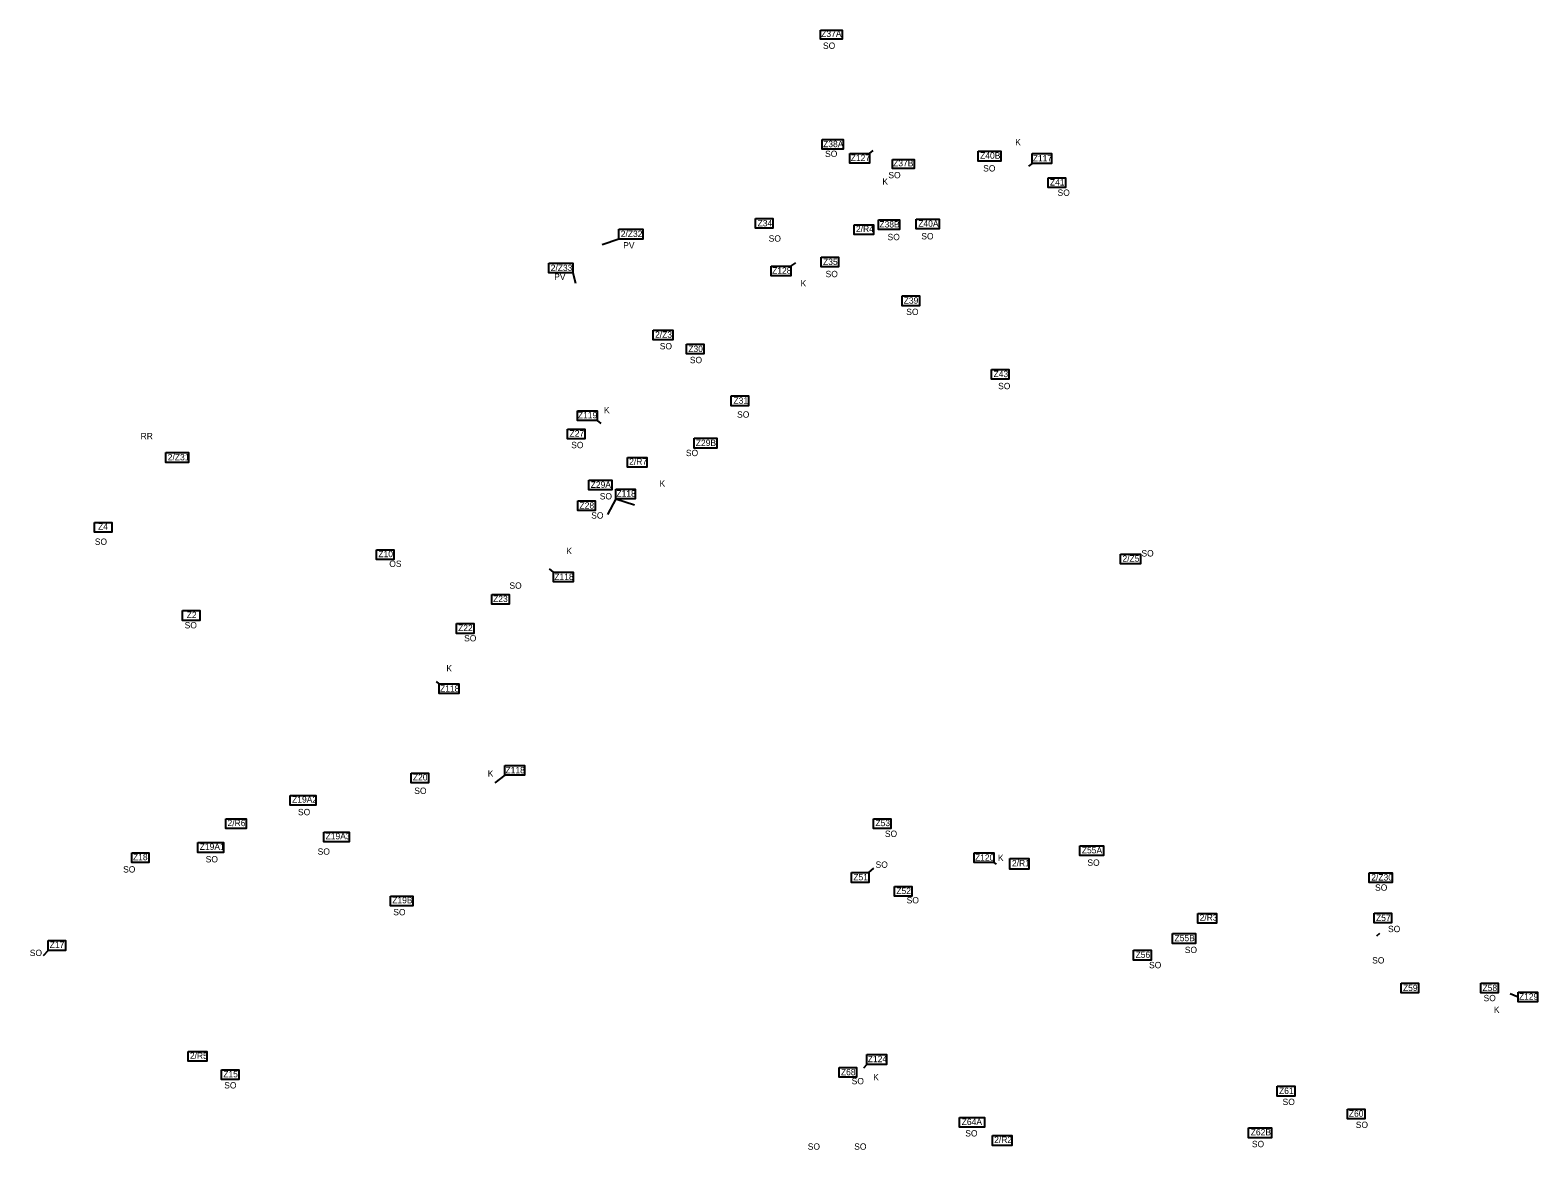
# Model space of a CAD drawing. Extents: x -443485 to -436070, y -1146628 to -1129894.
# Drawn here: x -443043 to -440666, y -1131659 to -1129894 of the extents above; entities that cross this region are included whole.
import ezdxf

# ---------------------------------------------------------------- set-up
doc = ezdxf.new("R2010")
doc.units = 0
for name, color, linetype in [('Vrstva 3', 7, 'Continuous'), ('Vrstva 4', 7, 'Continuous'), ('Vrstva 8', 7, 'Continuous')]:
    doc.layers.add(name, color=color, linetype=linetype)

msp = doc.modelspace()

# ---------------------------------------------------------------- linework, layer by layer
at = {"layer": 'Vrstva 3'}
for p, q in [((-442115.2, -1130223.5), (-442141.4, -1130232.8)), ((-442187.7, -1130277), (-442183.3, -1130293.2)), ((-441721, -1131222.3), (-441712.8, -1131215.4)), ((-443014.7, -1131344.8), (-443022.4, -1131353.5))]:
    msp.add_line(p, q, dxfattribs=at)
for points in [[(-441797.2, -1129894.2), (-441763, -1129894.2), (-441763, -1129908.3), (-441797.2, -1129908.3)], [(-441794.3, -1130066.6), (-441761.2, -1130066.6), (-441761.2, -1130082), (-441794.3, -1130082)], [(-441548.8, -1130085.1), (-441512.7, -1130085.1), (-441512.7, -1130100.5), (-441548.8, -1130100.5)], [(-441683.8, -1130098.2), (-441649.6, -1130098.2), (-441649.6, -1130112.3), (-441683.8, -1130112.3)], [(-441438.1, -1130126.8), (-441410.7, -1130126.8), (-441410.7, -1130142.2), (-441438.1, -1130142.2)], [(-441899.4, -1130191.2), (-441872.1, -1130191.2), (-441872.1, -1130206.6), (-441899.4, -1130206.6)], [(-441744, -1130200.9), (-441713.8, -1130200.9), (-441713.8, -1130216.3), (-441744, -1130216.3)], [(-441705.6, -1130193.1), (-441672.5, -1130193.1), (-441672.5, -1130208.5), (-441705.6, -1130208.5)], [(-441646.3, -1130192.2), (-441610.2, -1130192.2), (-441610.2, -1130207.6), (-441646.3, -1130207.6)], [(-442115.2, -1130208.1), (-442077.3, -1130208.1), (-442077.3, -1130223.5), (-442115.2, -1130223.5)], [(-441796.3, -1130252.1), (-441768.9, -1130252.1), (-441768.9, -1130267.5), (-441796.3, -1130267.5)], [(-442225.5, -1130261.6), (-442187.7, -1130261.6), (-442187.7, -1130277), (-442225.5, -1130277)], [(-441668.4, -1130313.2), (-441641, -1130313.2), (-441641, -1130328.6), (-441668.4, -1130328.6)], [(-442061.1, -1130366.9), (-442029.9, -1130366.9), (-442029.9, -1130382.3), (-442061.1, -1130382.3)], [(-442008.5, -1130389.3), (-441981.2, -1130389.3), (-441981.2, -1130404.7), (-442008.5, -1130404.7)], [(-441527.5, -1130428.9), (-441500.2, -1130428.9), (-441500.2, -1130444.3), (-441527.5, -1130444.3)], [(-441937.8, -1130470.9), (-441910.5, -1130470.9), (-441910.5, -1130486.3), (-441937.8, -1130486.3)], [(-442196.2, -1130523), (-442168.8, -1130523), (-442168.8, -1130538.4), (-442196.2, -1130538.4)], [(-441996.3, -1130537.6), (-441960.5, -1130537.6), (-441960.5, -1130553), (-441996.3, -1130553)], [(-442829.3, -1130560.1), (-442793.4, -1130560.1), (-442793.4, -1130575.5), (-442829.3, -1130575.5)], [(-442101.5, -1130567.8), (-442071, -1130567.8), (-442071, -1130583.2), (-442101.5, -1130583.2)], [(-442162.1, -1130603.5), (-442126, -1130603.5), (-442126, -1130618.9), (-442162.1, -1130618.9)], [(-442179.7, -1130636.2), (-442152.3, -1130636.2), (-442152.3, -1130651.6), (-442179.7, -1130651.6)], [(-442941.5, -1130670.1), (-442914.2, -1130670.1), (-442914.2, -1130685.5), (-442941.5, -1130685.5)], [(-442497.1, -1130713.3), (-442469.7, -1130713.3), (-442469.7, -1130728.7), (-442497.1, -1130728.7)], [(-441324.3, -1130720), (-441292.6, -1130720), (-441292.6, -1130735.4), (-441324.3, -1130735.4)], [(-442315.4, -1130783.8), (-442288.1, -1130783.8), (-442288.1, -1130799.2), (-442315.4, -1130799.2)], [(-442802.8, -1130809.3), (-442775.4, -1130809.3), (-442775.4, -1130824.7), (-442802.8, -1130824.7)], [(-442370.9, -1130829.7), (-442343.6, -1130829.7), (-442343.6, -1130845.1), (-442370.9, -1130845.1)], [(-442442.5, -1131065.5), (-442415.2, -1131065.5), (-442415.2, -1131080.9), (-442442.5, -1131080.9)], [(-442633, -1131100.5), (-442592.8, -1131100.5), (-442592.8, -1131115.9), (-442633, -1131115.9)], [(-442734.7, -1131137.5), (-442702.3, -1131137.5), (-442702.3, -1131152.9), (-442734.7, -1131152.9)], [(-441713.6, -1131137.4), (-441686.3, -1131137.4), (-441686.3, -1131152.8), (-441713.6, -1131152.8)], [(-442778.5, -1131175), (-442738.3, -1131175), (-442738.3, -1131190.4), (-442778.5, -1131190.4)], [(-442580.2, -1131158.4), (-442540, -1131158.4), (-442540, -1131173.8), (-442580.2, -1131173.8)], [(-441388.2, -1131179.9), (-441351.2, -1131179.9), (-441351.2, -1131195.3), (-441388.2, -1131195.3)], [(-442883, -1131190.9), (-442855.7, -1131190.9), (-442855.7, -1131206.3), (-442883, -1131206.3)], [(-441498.8, -1131200.2), (-441468.7, -1131200.2), (-441468.7, -1131216.6), (-441498.8, -1131216.6)], [(-441748.4, -1131222.3), (-441721, -1131222.3), (-441721, -1131237.7), (-441748.4, -1131237.7)], [(-440932, -1131222.5), (-440896.2, -1131222.5), (-440896.2, -1131237.9), (-440932, -1131237.9)], [(-441680.5, -1131244), (-441653.2, -1131244), (-441653.2, -1131259.4), (-441680.5, -1131259.4)], [(-442475.1, -1131259.2), (-442439.9, -1131259.2), (-442439.9, -1131274.6), (-442475.1, -1131274.6)], [(-441202.2, -1131286.7), (-441173.1, -1131286.7), (-441173.1, -1131302.1), (-441202.2, -1131302.1)], [(-440924.2, -1131286.2), (-440896.8, -1131286.2), (-440896.8, -1131301.6), (-440924.2, -1131301.6)], [(-441242.1, -1131318.4), (-441206.1, -1131318.4), (-441206.1, -1131333.8), (-441242.1, -1131333.8)], [(-443014.7, -1131329.4), (-442987.3, -1131329.4), (-442987.3, -1131344.8), (-443014.7, -1131344.8)], [(-441303.5, -1131344.7), (-441276.1, -1131344.7), (-441276.1, -1131360.1), (-441303.5, -1131360.1)], [(-440882, -1131396.5), (-440854.6, -1131396.5), (-440854.6, -1131411.9), (-440882, -1131411.9)], [(-440756.3, -1131396.5), (-440728.9, -1131396.5), (-440728.9, -1131411.9), (-440756.3, -1131411.9)], [(-442794, -1131504.3), (-442764.4, -1131504.3), (-442764.4, -1131519.7), (-442794, -1131519.7)], [(-442741.6, -1131532.9), (-442714.2, -1131532.9), (-442714.2, -1131548.2), (-442741.6, -1131548.2)], [(-441767.9, -1131529.5), (-441740.5, -1131529.5), (-441740.5, -1131544.9), (-441767.9, -1131544.9)], [(-441077, -1131559.1), (-441049.6, -1131559.1), (-441049.6, -1131574.5), (-441077, -1131574.5)], [(-441577.9, -1131608.3), (-441538.5, -1131608.3), (-441538.5, -1131623.7), (-441577.9, -1131623.7)], [(-440966.6, -1131595.2), (-440939.2, -1131595.2), (-440939.2, -1131610.6), (-440966.6, -1131610.6)], [(-441122.2, -1131624.7), (-441086, -1131624.7), (-441086, -1131640.1), (-441122.2, -1131640.1)], [(-441526.1, -1131636.8), (-441495.7, -1131636.8), (-441495.7, -1131652.2), (-441526.1, -1131652.2)]]:
    msp.add_lwpolyline(points, close=True, dxfattribs=at)
at = {"layer": 'Vrstva 8'}
for p, q in [((-441720.1, -1130088.6), (-441714.3, -1130084)), ((-441463.6, -1130104.2), (-441469.4, -1130108.5)), ((-441844, -1130266.2), (-441836.1, -1130260.9)), ((-442149.3, -1130509.6), (-442143.6, -1130514.2)), ((-442119.9, -1130633.2), (-442133, -1130657.8)), ((-442119.9, -1130633.2), (-442090.5, -1130642.7)), ((-442217.8, -1130748.4), (-442224.2, -1130743.6)), ((-442398, -1130924.7), (-442402.3, -1130921.1)), ((-442294.8, -1131068.6), (-442310.6, -1131080.6)), ((-441523.9, -1131206.4), (-441520.2, -1131209.2)), ((-440920.2, -1131322), (-440915.5, -1131317.9)), ((-440697.5, -1131418.4), (-440709.9, -1131413.3)), ((-441724, -1131524.5), (-441729.4, -1131530.4))]:
    msp.add_line(p, q, dxfattribs=at)
for points in [[(-441750.9, -1130088.6), (-441720.1, -1130088.6), (-441720.1, -1130104), (-441750.9, -1130104)], [(-441463.6, -1130088.8), (-441432.8, -1130088.8), (-441432.8, -1130104.2), (-441463.6, -1130104.2)], [(-441874.8, -1130266.2), (-441844, -1130266.2), (-441844, -1130281.6), (-441874.8, -1130281.6)], [(-442180.1, -1130494.2), (-442149.3, -1130494.2), (-442149.3, -1130509.6), (-442180.1, -1130509.6)], [(-442119.9, -1130617.8), (-442089.2, -1130617.8), (-442089.2, -1130633.2), (-442119.9, -1130633.2)], [(-442217.8, -1130748.4), (-442187, -1130748.4), (-442187, -1130763.8), (-442217.8, -1130763.8)], [(-442398, -1130924.7), (-442367.2, -1130924.7), (-442367.2, -1130940.1), (-442398, -1130940.1)], [(-442294.8, -1131053.2), (-442264, -1131053.2), (-442264, -1131068.6), (-442294.8, -1131068.6)], [(-441554.7, -1131191), (-441523.9, -1131191), (-441523.9, -1131206.4), (-441554.7, -1131206.4)], [(-440697.5, -1131410.7), (-440666.8, -1131410.7), (-440666.8, -1131426.1), (-440697.5, -1131426.1)], [(-441724, -1131509.1), (-441693.3, -1131509.1), (-441693.3, -1131524.5), (-441724, -1131524.5)]]:
    msp.add_lwpolyline(points, close=True, dxfattribs=at)

# ---------------------------------------------------------------- texts
at = {"layer": 'Vrstva 3'}
for s, p in [('Z37A', (-441796, -1129904.9)), ('Z38A', (-441793, -1130078.7)), ('Z40B', (-441545.5, -1130096.9)), ('Z37B', (-441682.6, -1130108.9)), ('Z41', (-441435.5, -1130139.1)), ('Z34', (-441896.3, -1130203.5)), ('2/R4', (-441741.2, -1130212.5)), ('Z38B', (-441704.3, -1130205.3)), ('Z40A', (-441643, -1130204.1)), ('2/Z32', (-442112, -1130220.3)), ('2/Z33', (-442222.4, -1130273.9)), ('Z35', (-441793.1, -1130264.3)), ('Z39', (-441665.9, -1130325.4)), ('2/Z3', (-442057.9, -1130379.2)), ('Z30', (-442005.5, -1130401.6)), ('Z43', (-441524.3, -1130441.2)), ('Z31', (-441934.3, -1130483.1)), ('Z27', (-442192.7, -1130535)), ('2/Z31', (-442826.1, -1130572.4)), ('Z29B', (-441993.7, -1130549.8)), ('Z29', (-441993.7, -1130549.8)), ('Z29', (-441993.7, -1130549.8)), ('2/R7', (-442098.7, -1130579.3)), ('Z29A', (-442159.4, -1130615.7)), ('Z29', (-442159.4, -1130615.7)), ('Z29', (-442159.4, -1130615.7)), ('Z28', (-442177, -1130648.4)), ('Z4', (-442936, -1130681.8)), ('Z10', (-442494.1, -1130725)), ('2/Z5', (-441321.1, -1130732.2)), ('Z23', (-442313.2, -1130795.7)), ('Z2', (-442796.3, -1130821.1)), ('Z22', (-442368.4, -1130841.6)), ('Z20', (-442439.7, -1131077)), ('Z19A2', (-442630.1, -1131112)), ('2/R6', (-442731.9, -1131149)), ('Z53', (-441710.5, -1131149)), ('Z19A1', (-442775.7, -1131186.4)), ('Z19A3', (-442577.3, -1131169.8)), ('Z18', (-442880.9, -1131202.7)), ('2/R1', (-441495.3, -1131212.4)), ('Z55A', (-441385.1, -1131192)), ('Z51', (-441745.4, -1131234.4)), ('2/Z30', (-440928.9, -1131234.7)), ('Z52', (-441677.6, -1131256)), ('Z19B', (-442472.2, -1131270.7)), ('2/R3', (-441199.4, -1131298.2)), ('Z57', (-440921.4, -1131298.6)), ('Z55B', (-441239, -1131330.4)), ('Z17', (-443012.2, -1131341)), ('Z56', (-441300.4, -1131356.7)), ('Z59', (-440878.9, -1131409)), ('Z58', (-440753.5, -1131409)), ('2/R5', (-442791.2, -1131515.8)), ('Z15', (-442738.6, -1131545)), ('Z68', (-441764.9, -1131541.8)), ('Z61', (-441074.3, -1131571.3)), ('Z60', (-440964.2, -1131607.1)), ('Z64A', (-441574.5, -1131620.1)), ('Z62B', (-441118.9, -1131636.5)), ('2/R2', (-441523.3, -1131648.3))]:
    msp.add_text(s, height=10, dxfattribs=at).set_placement(p)
at = {"layer": 'Vrstva 4'}
for s, p in [('SO', (-441793.2, -1129923.7)), ('SO', (-441789.9, -1130094.1)), ('K', (-441490.1, -1130075.8)), ('SO', (-441540.7, -1130117)), ('K', (-441699.6, -1130137.8)), ('SO', (-441690.1, -1130127.7)), ('SO', (-441423.4, -1130155.4)), ('PV', (-442108.2, -1130238.4)), ('SO', (-441878.8, -1130227.6)), ('SO', (-441691.4, -1130225.3)), ('SO', (-441638.2, -1130224.1)), ('SO', (-441789.1, -1130283.6)), ('PV', (-442217, -1130288)), ('K', (-441828.5, -1130298.3)), ('SO', (-441661.9, -1130343.3)), ('SO', (-442050.5, -1130397.4)), ('SO', (-442003.1, -1130419.2)), ('SO', (-441517.1, -1130460.2)), ('K', (-442138.4, -1130498.1)), ('SO', (-441928.6, -1130505.1)), ('RR', (-442868.9, -1130539)), ('SO', (-442190.1, -1130553.2)), ('SO', (-442009.3, -1130565.7)), ('K', (-442050.9, -1130613.8)), ('SO', (-442145.1, -1130634)), ('SO', (-442158.6, -1130664.2)), ('SO', (-442941.1, -1130705.6)), ('K', (-442197.8, -1130720.2)), ('SO', (-441291.2, -1130723.9)), ('OS', (-442476.9, -1130740.4)), ('SO', (-442287.5, -1130774.8)), ('SO', (-442799.5, -1130837.3)), ('SO', (-442358.9, -1130857.8)), ('K', (-442386.9, -1130905.2)), ('K', (-442321.7, -1131071)), ('SO', (-442437.5, -1131098.2)), ('SO', (-442620.8, -1131131.8)), ('SO', (-441695.6, -1131166)), ('SO', (-442766.3, -1131206.2)), ('SO', (-442589.8, -1131194.1)), ('SO', (-441710.3, -1131214.7)), ('K', (-441517.4, -1131204)), ('SO', (-441376.4, -1131211.5)), ('SO', (-442896.5, -1131222.1)), ('SO', (-440922.9, -1131250.8)), ('SO', (-441661.3, -1131270.8)), ('SO', (-442470.6, -1131289.5)), ('SO', (-440902.5, -1131316.1)), ('SO', (-443043.6, -1131353.8)), ('SO', (-441222.8, -1131349.1)), ('SO', (-441279.2, -1131373)), ('SO', (-440927.5, -1131365.5)), ('SO', (-440751.9, -1131425)), ('K', (-440735.6, -1131443.4)), ('SO', (-442737.1, -1131562.5)), ('SO', (-441748, -1131555.9)), ('K', (-441714.1, -1131549.7)), ('SO', (-441068.7, -1131588.7)), ('SO', (-441568.9, -1131638.2)), ('SO', (-440953.3, -1131624.8)), ('SO', (-441817.2, -1131659.1)), ('SO', (-441744, -1131659.1)), ('SO', (-441117.1, -1131655.1))]:
    msp.add_text(s, height=10, dxfattribs=at).set_placement(p)
at = {"layer": 'Vrstva 8'}
for s, p in [('Z127', (-441749.5, -1130100.6)), ('Z117', (-441462.5, -1130101.2)), ('Z128', (-441873.4, -1130278.2)), ('Z119', (-442179.6, -1130506.2)), ('Z118', (-442118.8, -1130629.6)), ('Z118', (-442216.7, -1130760.9)), ('Z118', (-442396.9, -1130937.1)), ('Z118', (-442293.7, -1131065.7)), ('Z120', (-441553.6, -1131203.5)), ('Z129', (-440696.1, -1131422.7)), ('Z124', (-441722.6, -1131521.1))]:
    msp.add_text(s, height=10, dxfattribs=at).set_placement(p)

doc.saveas('drawing.dxf')
